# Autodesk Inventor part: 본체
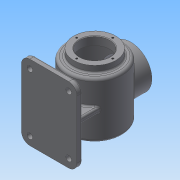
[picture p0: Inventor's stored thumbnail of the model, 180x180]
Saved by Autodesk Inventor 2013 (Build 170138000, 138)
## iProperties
Created: 2016-09
Part Number: 본체
Material: Generic
Document SubType Name: Modeling
Designer: Administrator
Density: 1 g/cm^3
Author: Administrator
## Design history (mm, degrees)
sketch "스케치1"
  geometry: C1 r 38 at (0, 0); 1 further point
  constraints: 1 centre point, 1 coincident
  dimensions: "d0" = 76 diameter of C1
extrude "돌출1" new body sketch "스케치1" distance "d1" = 12; taper "d2" = 0 deg
sketch "스케치2"
  geometry: C1 r 38 at (0, 0) reference; C2 r 50 at (0, 0)
  constraints: 1 centre point, 1 coincident
  dimensions: "d3" = 100 diameter of C2
extrude "돌출2" join sketch "스케치2" distance "d4" = 110; taper "d5" = 0 deg
node "작업 평면1"
sketch "스케치3"
  geometry: L1 (0, 0)-(0, -122); C1 r 38 at (0, -61)
  constraints: 2 end point, 1 centre point, 1 midpoint, 1 vertical
  dimensions: "d7" = 122 distance of L1.start L1.end; "d8" = 76 diameter of C1
extrude "돌출3" join sketch "스케치3" stored distance "d9" = 110; taper "d10" = 0 deg
node "작업 평면2"
sketch "스케치4"
  geometry: L1 (50, -12)-(-50, -12) reference; L2 (-50, -122)-(50, -122) reference; L3 (-38, -12)-(38, -12) reference; L4 (-38, 0)-(38, 0) reference; L5 (50, -61)-(50, 6.5); L6 (50, 6.5)-(-50, 6.5); L7 (-50, 6.5)-(-50, -128.5); L8 (-50, -128.5)-(50, -128.5); L9 (50, -128.5)-(50, -61); 1 further point
  constraints: 10 end point, 2 perpendicular, 1 parallel, 1 other
extrude "돌출4" join sketch "스케치4" distance "d17" = 10; taper "d18" = 0 deg
sketch "스케치5"
  geometry: L1 (-72, -21)-(21.167, -29.151); 1 further point
  constraints: 2 end point
node "작업 평면3"
sketch "스케치6"
  geometry: L1 (0, 0)-(40, 0); L2 (40, 0)-(40, -82); L3 (40, -82)-(-40, -82); L4 (-40, -82)-(-40, 0); L5 (-40, 0)-(0, 0)
  constraints: 10 end point, 3 perpendicular, 1 horizontal, 1 parallel
extrude "돌출5" join sketch "스케치6" stored distance "d28" = 10; taper "d29" = 0 deg
feature "리브1" dims "d30" = 1, "d31" = 10, "d32" = 0, "d33" = 0, "d34" = 1, "d35" = 1
sketch "스케치7"
  geometry: L1 (0, 0)-(0, -122); L2 (0, -122)-(50, -122); L3 (0, -122)-(-50, -122); L4 (0, -122)-(0, -122); L5 (-50, -110.562)-(-50, -122); L6 (-50, -122)-(0, -122); A1 r 115 centre (0, -7) between (-50, -110.562) and (0, -122)
  constraints: 12 end point, 2 perpendicular, 2 point on circle, 1 centre point, 1 collinear, 1 tangent, 1 vertical
revolve "회전1" sketch "스케치7" stored, may be unused: angle "d40" = 90 deg
sketch "스케치8"
  geometry: L1 (50, -110.562)-(50, -12); L2 (50, -12)-(-50, -12) reference; L3 (47, -15)-(47, -108.661); L4 (47, -15)-(0, -15); L5 (0, -12)-(0, -122); A1 r 115 centre (0, -7) between (-50, -110.562) and (50, -110.562) reference; A2 r 112 centre (0, -7) between (0, -119) and (47, -108.661); 1 further point
  constraints: 8 end point, 3 point on circle, 3 point on line, 1 centre point, 1 midpoint, 1 parallel
revolve "회전2" sketch "스케치8" stored, may be unused: angle "d45" = 90 deg
sketch "스케치9"
  geometry: C1 r 38 at (0, 0) reference; C2 r 27 at (0, 0)
  constraints: 1 centre point, 1 coincident
  dimensions: "d46" = 54 diameter of C2
extrude "돌출6" cut sketch "스케치9" distance "d47" = 15; taper "d48" = 0 deg
sketch "스케치10"
  geometry: C1 r 38 at (0, 0) reference; C2 r 27 at (0, 0); 1 further point
  constraints: 1 centre point, 1 coincident
  dimensions: "d49" = 54 diameter of C2
extrude "돌출7" cut sketch "스케치10" stored distance "d50" = 15; taper "d51" = 0 deg
fillet "모깎기1" dims "d52" = 15, "d53" = 5, "d54" = 2, "d55" = 3
fillet "모깎기2" dims "d56" = 3
chamfer "모따기1" distance "d57" = 1; stored, may be unused: second distance "d58" = 2, angle "d59" = 45 deg
sketch "스케치11"
  geometry: 1 further point
hole "구멍1" sketch "스케치11" at (0, 32.5) diameter "d61" = 3.459; stored, may be unused: countersink angle "d65" = 90 deg, drill point angle "d67" = 118 deg; dims "d62" = 8, "d63" = 4, "d64" = 2, "d66" = 10
sketch "스케치12"
  geometry: 2 further points
hole "구멍2" sketch "스케치12" at (0, 32.5) diameter "d72" = 3.459; stored, may be unused: countersink angle "d76" = 90 deg, drill point angle "d78" = 118 deg; dims "d73" = 8, "d74" = 4, "d75" = 2, "d77" = 10
sketch "스케치13"
  geometry: C1 r 5 at (-35, -8.5); A1 r 15 centre (-35, -8.5) between (-35, 6.5) and (-50, -8.5) reference; 1 further point
  constraints: 1 centre point, 1 coincident
  dimensions: "d82" = 10 diameter of C1
extrude "돌출8" cut sketch "스케치13" stored distance "d83" = 15; taper "d84" = 0 deg
node "작업 평면4"
node "작업 평면5"
sketch "스케치14"
  geometry: 2 further points
  constraints: 1 other
feature "엠보싱1" sketch "스케치14" dims "d87" = 1, "d88" = 0
node "솔리드1"
mirror "대칭1"
pattern_circular "원형 패턴1" dims angle "d69" = 360 deg
pattern_circular "원형 패턴2" dims angle "d80" = 360 deg
mirror "대칭2"
mirror "대칭3"
node "투영된 루프1"
node "투영된 루프2"
other parameters: "d6" = 65, "d11" = -82, "d24" = -61, "d85" = 0, "d86" = -122.5
